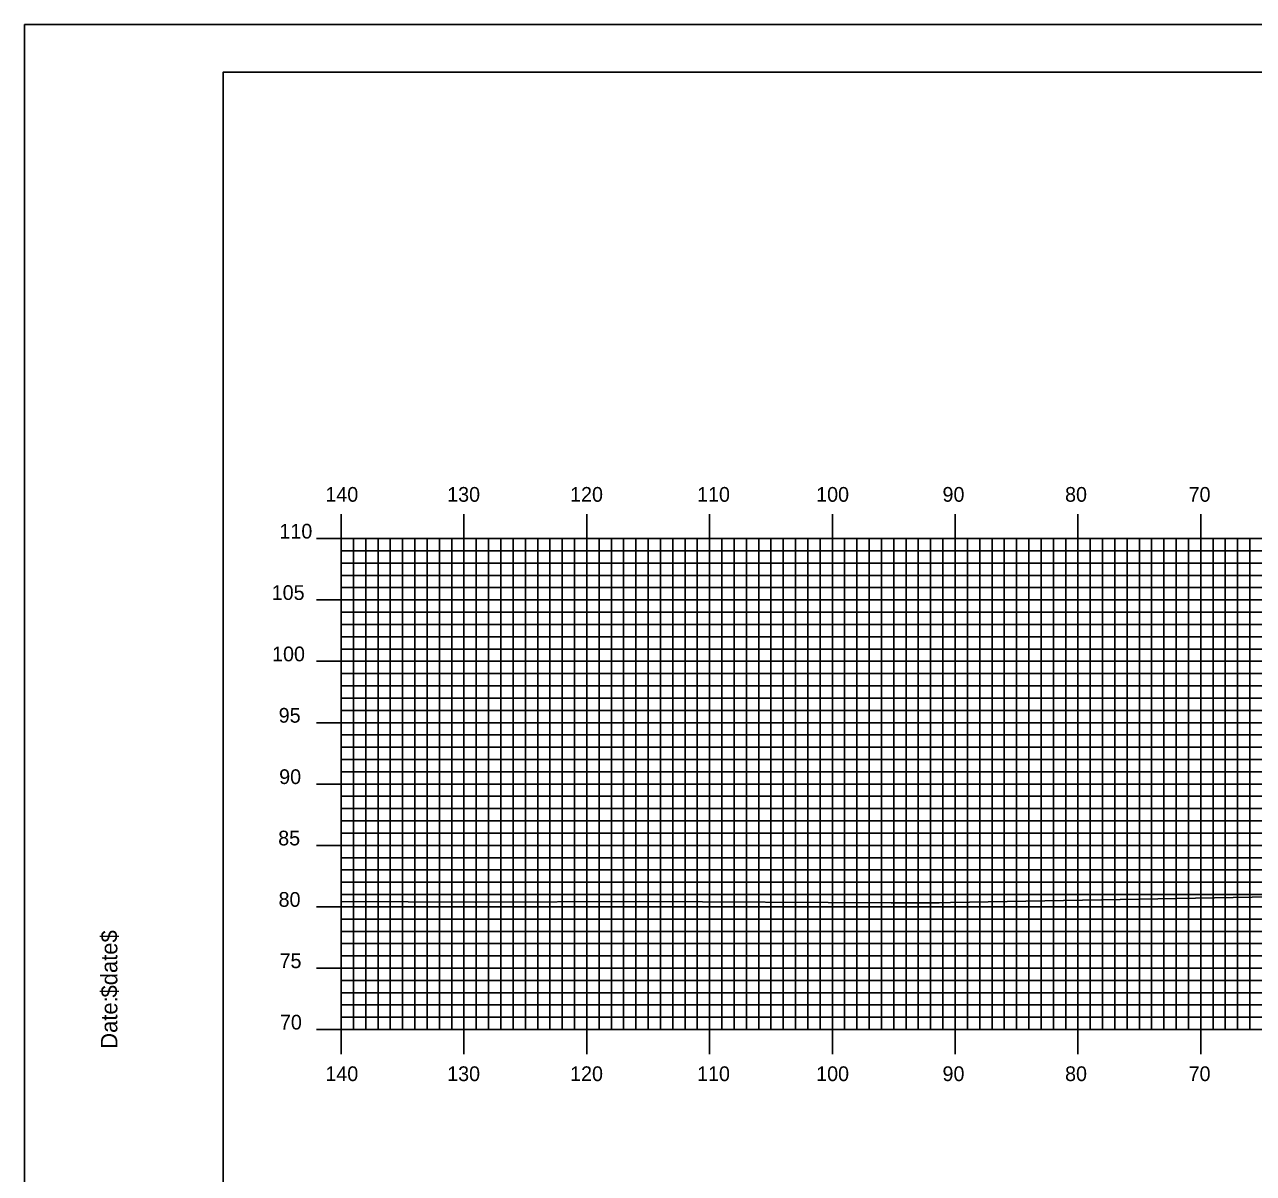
# Model space of a CAD drawing. Extents: x 1759036 to 1759380, y 442591 to 442811.
# Drawn here: x 1759036.4 to 1759136.4, y 442716.9 to 442810.5 of the extents above; entities that cross this region are included whole.
import ezdxf

# ---------------------------------------------------------------- set-up
doc = ezdxf.new("R2010")
doc.units = 0
for name, color, linetype in [('BORDER', 7, 'Continuous'), ('H_V ANNOTATION', 7, 'Continuous'), ('MAJOR', 7, 'Continuous'), ('MINOR', 7, 'Continuous'), ('PLOT BOUNDARY', 7, 'Continuous'), ('S_Roadway_Centerline', 7, 'Continuous')]:
    doc.layers.add(name, color=color, linetype=linetype)

msp = doc.modelspace()

# ---------------------------------------------------------------- linework, layer by layer
at = {"layer": 'BORDER'}
msp.add_lwpolyline([(1759052.56, 442596.67), (1759372.56, 442596.67), (1759372.56, 442806.67), (1759052.56, 442806.67)], close=True, dxfattribs=at)
at = {"layer": 'MAJOR'}
for p, q in [((1759062.16, 442770.67), (1759062.16, 442768.67)), ((1759072.16, 442770.67), (1759072.16, 442768.67)), ((1759082.16, 442770.67), (1759082.16, 442768.67)), ((1759092.16, 442770.67), (1759092.16, 442768.67)), ((1759102.16, 442770.67), (1759102.16, 442768.67)), ((1759112.16, 442770.67), (1759112.16, 442768.67)), ((1759122.16, 442770.67), (1759122.16, 442768.67)), ((1759132.16, 442770.67), (1759132.16, 442768.67)), ((1759060.16, 442768.67), (1759062.16, 442768.67)), ((1759062.16, 442768.67), (1759342.16, 442768.67)), ((1759062.16, 442728.67), (1759062.16, 442768.67)), ((1759062.16, 442728.67), (1759062.16, 442768.67)), ((1759062.16, 442768.67), (1759342.16, 442768.67)), ((1759072.16, 442728.67), (1759072.16, 442768.67)), ((1759082.16, 442728.67), (1759082.16, 442768.67)), ((1759092.16, 442728.67), (1759092.16, 442768.67)), ((1759102.16, 442728.67), (1759102.16, 442768.67)), ((1759112.16, 442728.67), (1759112.16, 442768.67)), ((1759122.16, 442728.67), (1759122.16, 442768.67)), ((1759132.16, 442728.67), (1759132.16, 442768.67)), ((1759060.16, 442763.67), (1759062.16, 442763.67)), ((1759062.16, 442763.67), (1759342.16, 442763.67)), ((1759060.16, 442758.67), (1759062.16, 442758.67)), ((1759062.16, 442758.67), (1759342.16, 442758.67)), ((1759060.16, 442753.67), (1759062.16, 442753.67)), ((1759062.16, 442753.67), (1759342.16, 442753.67)), ((1759060.16, 442748.67), (1759062.16, 442748.67)), ((1759062.16, 442748.67), (1759342.16, 442748.67)), ((1759060.16, 442743.67), (1759062.16, 442743.67)), ((1759062.16, 442743.67), (1759342.16, 442743.67)), ((1759060.16, 442738.67), (1759062.16, 442738.67)), ((1759062.16, 442738.67), (1759342.16, 442738.67)), ((1759060.16, 442733.67), (1759062.16, 442733.67)), ((1759062.16, 442733.67), (1759342.16, 442733.67)), ((1759060.16, 442728.67), (1759062.16, 442728.67)), ((1759062.16, 442728.67), (1759342.16, 442728.67)), ((1759062.16, 442728.67), (1759342.16, 442728.67)), ((1759062.16, 442726.66), (1759062.16, 442728.67)), ((1759072.16, 442726.66), (1759072.16, 442728.67)), ((1759082.16, 442726.66), (1759082.16, 442728.67)), ((1759092.16, 442726.66), (1759092.16, 442728.67)), ((1759102.16, 442726.66), (1759102.16, 442728.67)), ((1759112.16, 442726.66), (1759112.16, 442728.67)), ((1759122.16, 442726.66), (1759122.16, 442728.67)), ((1759132.16, 442726.66), (1759132.16, 442728.67))]:
    msp.add_line(p, q, dxfattribs=at)
at = {"layer": 'MINOR'}
for p, q in [((1759063.16, 442728.67), (1759063.16, 442768.67)), ((1759064.16, 442728.67), (1759064.16, 442768.67)), ((1759065.16, 442728.67), (1759065.16, 442768.67)), ((1759066.16, 442728.67), (1759066.16, 442768.67)), ((1759067.16, 442728.67), (1759067.16, 442768.67)), ((1759068.16, 442728.67), (1759068.16, 442768.67)), ((1759069.16, 442728.67), (1759069.16, 442768.67)), ((1759070.16, 442728.67), (1759070.16, 442768.67)), ((1759071.16, 442728.67), (1759071.16, 442768.67)), ((1759073.16, 442728.67), (1759073.16, 442768.67)), ((1759074.16, 442728.67), (1759074.16, 442768.67)), ((1759075.16, 442728.67), (1759075.16, 442768.67)), ((1759076.16, 442728.67), (1759076.16, 442768.67)), ((1759077.16, 442728.67), (1759077.16, 442768.67)), ((1759078.16, 442728.67), (1759078.16, 442768.67)), ((1759079.16, 442728.67), (1759079.16, 442768.67)), ((1759080.16, 442728.67), (1759080.16, 442768.67)), ((1759081.16, 442728.67), (1759081.16, 442768.67)), ((1759083.16, 442728.67), (1759083.16, 442768.67)), ((1759084.16, 442728.67), (1759084.16, 442768.67)), ((1759085.16, 442728.67), (1759085.16, 442768.67)), ((1759086.16, 442728.67), (1759086.16, 442768.67)), ((1759087.16, 442728.67), (1759087.16, 442768.67)), ((1759088.16, 442728.67), (1759088.16, 442768.67)), ((1759089.16, 442728.67), (1759089.16, 442768.67)), ((1759090.16, 442728.67), (1759090.16, 442768.67)), ((1759091.16, 442728.67), (1759091.16, 442768.67)), ((1759093.16, 442728.67), (1759093.16, 442768.67)), ((1759094.16, 442728.67), (1759094.16, 442768.67)), ((1759095.16, 442728.67), (1759095.16, 442768.67)), ((1759096.16, 442728.67), (1759096.16, 442768.67)), ((1759097.16, 442728.67), (1759097.16, 442768.67)), ((1759098.16, 442728.67), (1759098.16, 442768.67)), ((1759099.16, 442728.67), (1759099.16, 442768.67)), ((1759100.16, 442728.67), (1759100.16, 442768.67)), ((1759101.16, 442728.67), (1759101.16, 442768.67)), ((1759103.16, 442728.67), (1759103.16, 442768.67)), ((1759104.16, 442728.67), (1759104.16, 442768.67)), ((1759105.16, 442728.67), (1759105.16, 442768.67)), ((1759106.16, 442728.67), (1759106.16, 442768.67)), ((1759107.16, 442728.67), (1759107.16, 442768.67)), ((1759108.16, 442728.67), (1759108.16, 442768.67)), ((1759109.16, 442728.67), (1759109.16, 442768.67)), ((1759110.16, 442728.67), (1759110.16, 442768.67)), ((1759111.16, 442728.67), (1759111.16, 442768.67)), ((1759113.16, 442728.67), (1759113.16, 442768.67)), ((1759114.16, 442728.67), (1759114.16, 442768.67)), ((1759115.16, 442728.67), (1759115.16, 442768.67)), ((1759116.16, 442728.67), (1759116.16, 442768.67)), ((1759117.16, 442728.67), (1759117.16, 442768.67)), ((1759118.16, 442728.67), (1759118.16, 442768.67)), ((1759119.16, 442728.67), (1759119.16, 442768.67)), ((1759120.16, 442728.67), (1759120.16, 442768.67)), ((1759121.16, 442728.67), (1759121.16, 442768.67)), ((1759123.16, 442728.67), (1759123.16, 442768.67)), ((1759124.16, 442728.67), (1759124.16, 442768.67)), ((1759125.16, 442728.67), (1759125.16, 442768.67)), ((1759126.16, 442728.67), (1759126.16, 442768.67)), ((1759127.16, 442728.67), (1759127.16, 442768.67)), ((1759128.16, 442728.67), (1759128.16, 442768.67)), ((1759129.16, 442728.67), (1759129.16, 442768.67)), ((1759130.16, 442728.67), (1759130.16, 442768.67)), ((1759131.16, 442728.67), (1759131.16, 442768.67)), ((1759133.16, 442728.67), (1759133.16, 442768.67)), ((1759134.16, 442728.67), (1759134.16, 442768.67)), ((1759135.16, 442728.67), (1759135.16, 442768.67)), ((1759136.16, 442728.67), (1759136.16, 442768.67)), ((1759062.16, 442767.67), (1759342.16, 442767.67)), ((1759062.16, 442767.67), (1759064.17, 442767.67)), ((1759062.16, 442766.67), (1759342.16, 442766.67)), ((1759062.16, 442766.67), (1759064.17, 442766.67)), ((1759062.16, 442765.67), (1759342.16, 442765.67)), ((1759062.16, 442765.67), (1759064.17, 442765.67)), ((1759062.16, 442764.67), (1759342.16, 442764.67)), ((1759062.16, 442764.67), (1759064.17, 442764.67)), ((1759062.16, 442762.67), (1759342.16, 442762.67)), ((1759062.16, 442762.67), (1759064.17, 442762.67)), ((1759062.16, 442761.67), (1759342.16, 442761.67)), ((1759062.16, 442761.67), (1759064.17, 442761.67)), ((1759062.16, 442760.67), (1759342.16, 442760.67)), ((1759062.16, 442760.67), (1759064.17, 442760.67)), ((1759062.16, 442759.67), (1759342.16, 442759.67)), ((1759062.16, 442759.67), (1759064.17, 442759.67)), ((1759062.16, 442757.67), (1759342.16, 442757.67)), ((1759062.16, 442757.67), (1759064.17, 442757.67)), ((1759062.16, 442756.67), (1759342.16, 442756.67)), ((1759062.16, 442756.67), (1759064.17, 442756.67)), ((1759062.16, 442755.67), (1759342.16, 442755.67)), ((1759062.16, 442755.67), (1759064.17, 442755.67)), ((1759062.16, 442754.67), (1759342.16, 442754.67)), ((1759062.16, 442754.67), (1759064.17, 442754.67)), ((1759062.16, 442752.67), (1759342.16, 442752.67)), ((1759062.16, 442752.67), (1759064.17, 442752.67)), ((1759062.16, 442751.67), (1759342.16, 442751.67)), ((1759062.16, 442751.67), (1759064.17, 442751.67)), ((1759062.16, 442750.67), (1759342.16, 442750.67)), ((1759062.16, 442750.67), (1759064.17, 442750.67)), ((1759062.16, 442749.67), (1759342.16, 442749.67)), ((1759062.16, 442749.67), (1759064.17, 442749.67)), ((1759062.16, 442747.67), (1759342.16, 442747.67)), ((1759062.16, 442747.67), (1759064.17, 442747.67)), ((1759062.16, 442746.67), (1759342.16, 442746.67)), ((1759062.16, 442746.67), (1759064.17, 442746.67)), ((1759062.16, 442745.67), (1759342.16, 442745.67)), ((1759062.16, 442745.67), (1759064.17, 442745.67)), ((1759062.16, 442744.67), (1759342.16, 442744.67)), ((1759062.16, 442744.67), (1759064.17, 442744.67)), ((1759062.16, 442742.67), (1759342.16, 442742.67)), ((1759062.16, 442742.67), (1759064.17, 442742.67)), ((1759062.16, 442741.67), (1759342.16, 442741.67)), ((1759062.16, 442741.67), (1759064.17, 442741.67)), ((1759062.16, 442740.67), (1759342.16, 442740.67)), ((1759062.16, 442740.67), (1759064.17, 442740.67)), ((1759062.16, 442739.67), (1759342.16, 442739.67)), ((1759062.16, 442739.67), (1759064.17, 442739.67)), ((1759062.16, 442737.67), (1759342.16, 442737.67)), ((1759062.16, 442737.67), (1759064.17, 442737.67)), ((1759062.16, 442736.67), (1759342.16, 442736.67)), ((1759062.16, 442736.67), (1759064.17, 442736.67)), ((1759062.16, 442735.67), (1759342.16, 442735.67)), ((1759062.16, 442735.67), (1759064.17, 442735.67)), ((1759062.16, 442734.67), (1759342.16, 442734.67)), ((1759062.16, 442734.67), (1759064.17, 442734.67)), ((1759062.16, 442732.67), (1759342.16, 442732.67)), ((1759062.16, 442732.67), (1759064.17, 442732.67)), ((1759062.16, 442731.67), (1759342.16, 442731.67)), ((1759062.16, 442731.67), (1759064.17, 442731.67)), ((1759062.16, 442730.67), (1759342.16, 442730.67)), ((1759062.16, 442730.67), (1759064.17, 442730.67)), ((1759062.16, 442729.67), (1759342.16, 442729.67)), ((1759062.16, 442729.67), (1759064.17, 442729.67))]:
    msp.add_line(p, q, dxfattribs=at)
at = {"layer": 'PLOT BOUNDARY'}
msp.add_lwpolyline([(1759036.37, 442590.55), (1759376.37, 442590.55), (1759376.37, 442810.55), (1759036.37, 442810.55)], close=True, dxfattribs=at)
at = {"layer": 'S_Roadway_Centerline'}
msp.add_lwpolyline([(1759062.16, 442739.1), (1759073.08, 442739.06), (1759086.45, 442739.09), (1759106.94, 442739), (1759110.85, 442739), (1759111.78, 442739.01), (1759147.1, 442739.64)], dxfattribs=at)

# ---------------------------------------------------------------- texts
at = {"layer": 'BORDER'}
for s, p in [('$date$', (1759043.93, 442731.28)), ('$date$', (1759043.93, 442731.28)), ('Date:', (1759043.93, 442727.1)), ('Date:', (1759043.93, 442727.1))]:
    msp.add_text(s, height=1.339, rotation=90, dxfattribs=at).set_placement(p)
at = {"layer": 'H_V ANNOTATION'}
for s, p in [('140', (1759060.87, 442771.67)), ('130', (1759070.79, 442771.67)), ('120', (1759080.8, 442771.67)), ('110', (1759091.14, 442771.67)), ('100', (1759100.84, 442771.67)), ('90', (1759111.13, 442771.67)), ('80', (1759121.11, 442771.67)), ('70', (1759131.17, 442771.67)), ('110', (1759057.13, 442768.67)), ('105', (1759056.5, 442763.67)), ('100', (1759056.53, 442758.67)), ('95', (1759057.07, 442753.67)), ('90', (1759057.11, 442748.67)), ('85', (1759057.03, 442743.67)), ('80', (1759057.06, 442738.67)), ('75', (1759057.14, 442733.67)), ('70', (1759057.17, 442728.67)), ('140', (1759060.87, 442724.47)), ('130', (1759070.79, 442724.47)), ('120', (1759080.8, 442724.47)), ('110', (1759091.14, 442724.47)), ('100', (1759100.84, 442724.47)), ('90', (1759111.13, 442724.47)), ('80', (1759121.11, 442724.47)), ('70', (1759131.17, 442724.47))]:
    msp.add_text(s, height=1.2, dxfattribs=at).set_placement(p)
at = {"layer": 'MAJOR'}
msp.add_text('-', height=0.012, dxfattribs=at).set_placement((1759062.15, 442728.67))

doc.saveas('drawing.dxf')
